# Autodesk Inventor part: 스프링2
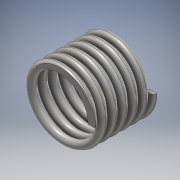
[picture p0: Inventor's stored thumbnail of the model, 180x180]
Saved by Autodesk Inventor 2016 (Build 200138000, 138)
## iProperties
Created: 2019-07
Part Number: 스프링2
Material: 강철, 탄소
Document SubType Name: Modeling
Designer: 602-01
Density: 7.85 g/cm^3
Appearance: 반연마
Mass: 7.69315 g
Surface Area: 20.0054 cm^2
Volume: 0.980019 cm^3
Author: 602-01
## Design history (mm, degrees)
sketch "스케치1"
  geometry: L1 (0, 0)-(8.5, 0); L2 (8.5, 0)-(8.5, 26); L3 (8.5, 26)-(0, 26); L4 (0, 26)-(0, 0); C1 r 1 at (8.5, 0)
  constraints: 8 end point, 2 parallel, 1 centre point, 1 coincident, 1 horizontal, 1 perpendicular
  dimensions: "d0" = 17 diameter of L2 L4; "d1" = 26 distance between parallel lines of L1 L3 (derived); "d2" = 2 diameter of C1
feature "코일1" sketch "스케치1" pitch "d3" = 10; turns "d5" = 6; dims "d4" = 26 (= d1), "d6" = 0, angle "d7" = 90 deg, angle "d8" = 90 deg, "d9" = 0, "d10" = 0
sketch "스케치2"
  geometry: L1 (-7.5, 0)-(-9.5, 0) reference; 1 further point
  constraints: 1 horizontal alignment
extrude "돌출1" cut sketch "스케치2" distance "d11" = 10; taper "d12" = 0 deg
node "작업 평면1"
sketch "스케치3"
  geometry: L1 (-1, 0)-(1, 0) reference; 1 further point
  constraints: 1 horizontal alignment
extrude "돌출2" cut sketch "스케치3" distance "d14" = 10; taper "d15" = 0 deg
node "솔리드1"
node "절단 모서리 투영1"
node "절단 모서리 투영2"
other parameters: "d13" = 90 deg
